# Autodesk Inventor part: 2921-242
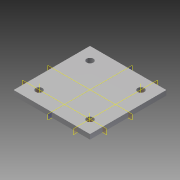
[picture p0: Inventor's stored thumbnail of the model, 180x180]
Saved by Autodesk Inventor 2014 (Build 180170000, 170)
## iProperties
Company: NHTSA/VRTC
Created: 2011-11
Part Number: 2921-242
Material: Steel
Document SubType Name: Modeling
Designer: Mike Vanvoorhis
Density: 7.85 g/cm^3
Project: CHILD SIDE IMPACT SLED
Description: PL 3/8" x 152.5 mm (6.0") x 152.5 mm (6.0")
Mass: 1691.76 g
Surface Area: 527.75 cm^2
Volume: 215.511 cm^3
Stock Number: IMPACTOR SUPPORT PLATE
Appearance: Steel
Author: Dave Walker
Title: IMPACTOR SUPPORT PLATE
Subject: Child Side Impact Sled
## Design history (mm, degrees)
node "Sketch1"
node "2921-1041"
workaxis "Work Axis5"
workaxis "Work Axis6"
workaxis "Work Axis7"
workplane "Work Plane4"
workplane "Work Plane5"
workplane "Work Plane6"
workplane "Work Plane7"
node "2921-104"
node "Base1"
